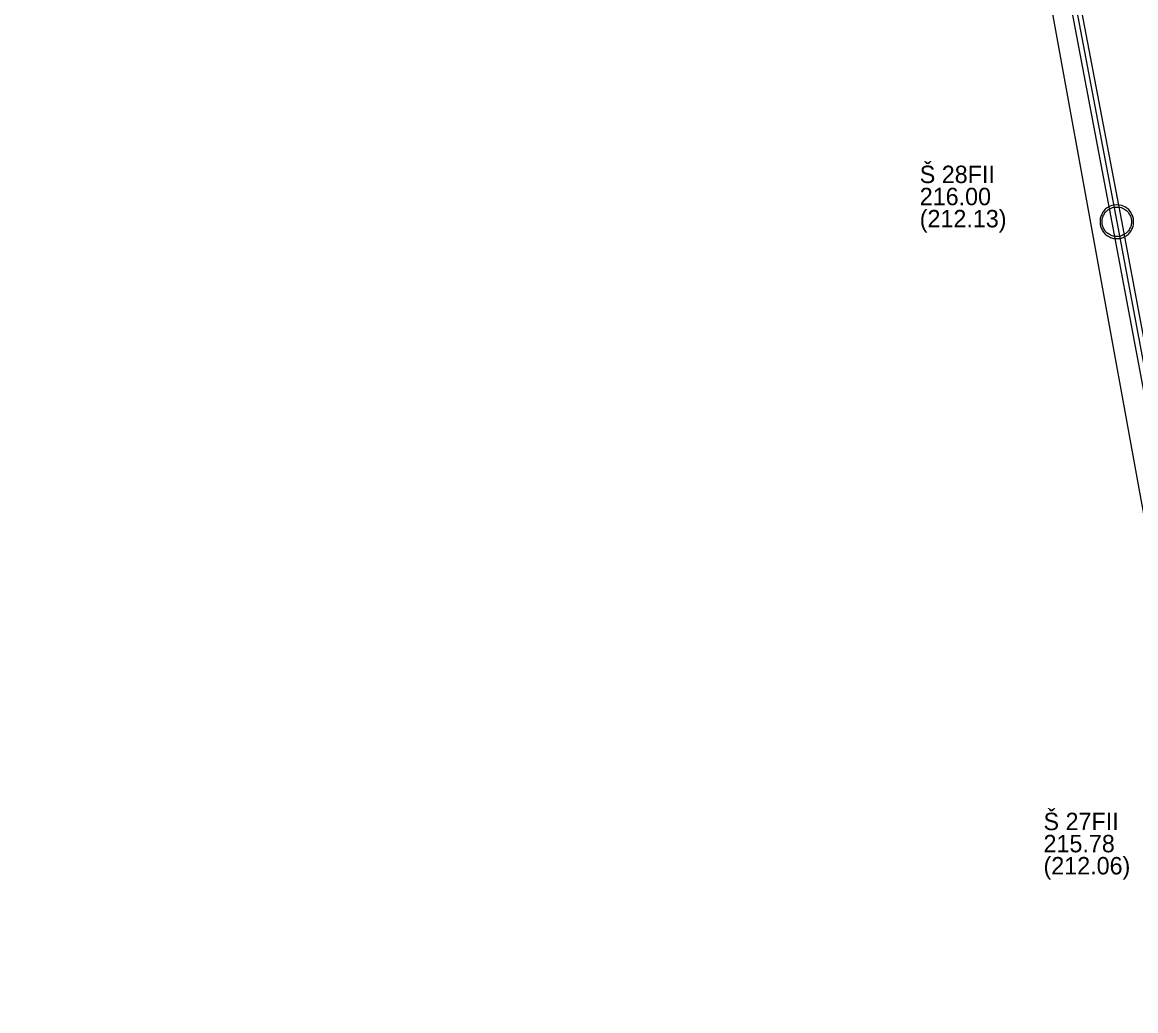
# Model space of a CAD drawing. Extents: x -592202 to -587539, y -1167222 to -1162672.
# Drawn here: x -589728.5 to -589645.4, y -1165732.1 to -1165658.4 of the extents above; entities that cross this region are included whole.
import ezdxf

# ---------------------------------------------------------------- set-up
doc = ezdxf.new("R2010")
doc.units = 0
for name, color, linetype in [('K Označení šachty', 7, 'Continuous'), ('K Stoka', 7, 'Continuous'), ('K Stoka - okraje', 7, 'Continuous'), ('K Šachta', 7, 'Continuous'), ('VP Přípojka', 7, 'Continuous')]:
    doc.layers.add(name, color=color, linetype=linetype)

msp = doc.modelspace()

# ---------------------------------------------------------------- linework, layer by layer
at = {"layer": 'K Stoka'}
for p, q in [((-589654.829, -1165631.02), (-589646.814, -1165673.226)), ((-589646.814, -1165673.226), (-589637.734, -1165721.632))]:
    msp.add_line(p, q, dxfattribs=at)
at = {"layer": 'K Stoka - okraje'}
for p, q in [((-589647.158, -1165673.291), (-589655.173, -1165631.085)), ((-589654.485, -1165630.955), (-589646.47, -1165673.161)), ((-589646.47, -1165673.161), (-589637.39, -1165721.567)), ((-589638.078, -1165721.697), (-589647.158, -1165673.291))]:
    msp.add_line(p, q, dxfattribs=at)
at = {"layer": 'K Šachta'}
for points in [[(-589646.815, -1165671.976), (-589646.5, -1165671.976), (-589646.201, -1165672.137), (-589645.902, -1165672.298), (-589645.733, -1165672.599), (-589645.564, -1165672.9), (-589645.564, -1165673.227), (-589645.564, -1165673.552), (-589645.729, -1165673.849), (-589645.894, -1165674.146), (-589646.191, -1165674.311), (-589646.489, -1165674.476), (-589646.815, -1165674.476), (-589647.139, -1165674.476), (-589647.437, -1165674.311), (-589647.734, -1165674.146), (-589647.899, -1165673.849), (-589648.064, -1165673.552), (-589648.064, -1165673.227), (-589648.064, -1165672.9), (-589647.896, -1165672.599), (-589647.728, -1165672.298), (-589647.43, -1165672.137), (-589647.131, -1165671.976), (-589646.815, -1165671.976)], [(-589646.814, -1165672.132), (-589647.091, -1165672.132), (-589647.353, -1165672.273), (-589647.615, -1165672.414), (-589647.761, -1165672.677), (-589647.908, -1165672.939), (-589647.908, -1165673.226), (-589647.908, -1165673.51), (-589647.763, -1165673.77), (-589647.618, -1165674.03), (-589647.358, -1165674.175), (-589647.097, -1165674.32), (-589646.814, -1165674.32), (-589646.531, -1165674.32), (-589646.27, -1165674.175), (-589646.01, -1165674.03), (-589645.865, -1165673.77), (-589645.72, -1165673.51), (-589645.72, -1165673.226), (-589645.72, -1165672.939), (-589645.869, -1165672.677), (-589646.017, -1165672.414), (-589646.278, -1165672.273), (-589646.539, -1165672.132), (-589646.814, -1165672.132)]]:
    msp.add_open_spline(points, degree=3, dxfattribs=at)
at = {"layer": 'VP Přípojka'}
msp.add_lwpolyline([(-589728.451, -1165612.785), (-589679.379, -1165609.846), (-589662.235, -1165606.59), (-589658.462, -1165621.553), (-589651.586, -1165657.874), (-589645.075, -1165693.676), (-589641.511, -1165712.779), (-589640.336, -1165718.539), (-589637.576, -1165732.062)], dxfattribs=at)

# ---------------------------------------------------------------- texts
at = {"layer": 'K Označení šachty'}
for s, p in [('Š 28FII', (-589661.512, -1165670.344)), ('216.00', (-589661.512, -1165671.994)), ('(212.13)', (-589661.512, -1165673.644)), ('Š 27FII', (-589652.279, -1165718.597)), ('215.78', (-589652.279, -1165720.247)), ('(212.06)', (-589652.279, -1165721.897))]:
    msp.add_text(s, height=1.3, dxfattribs=at).set_placement(p)

doc.saveas('drawing.dxf')
